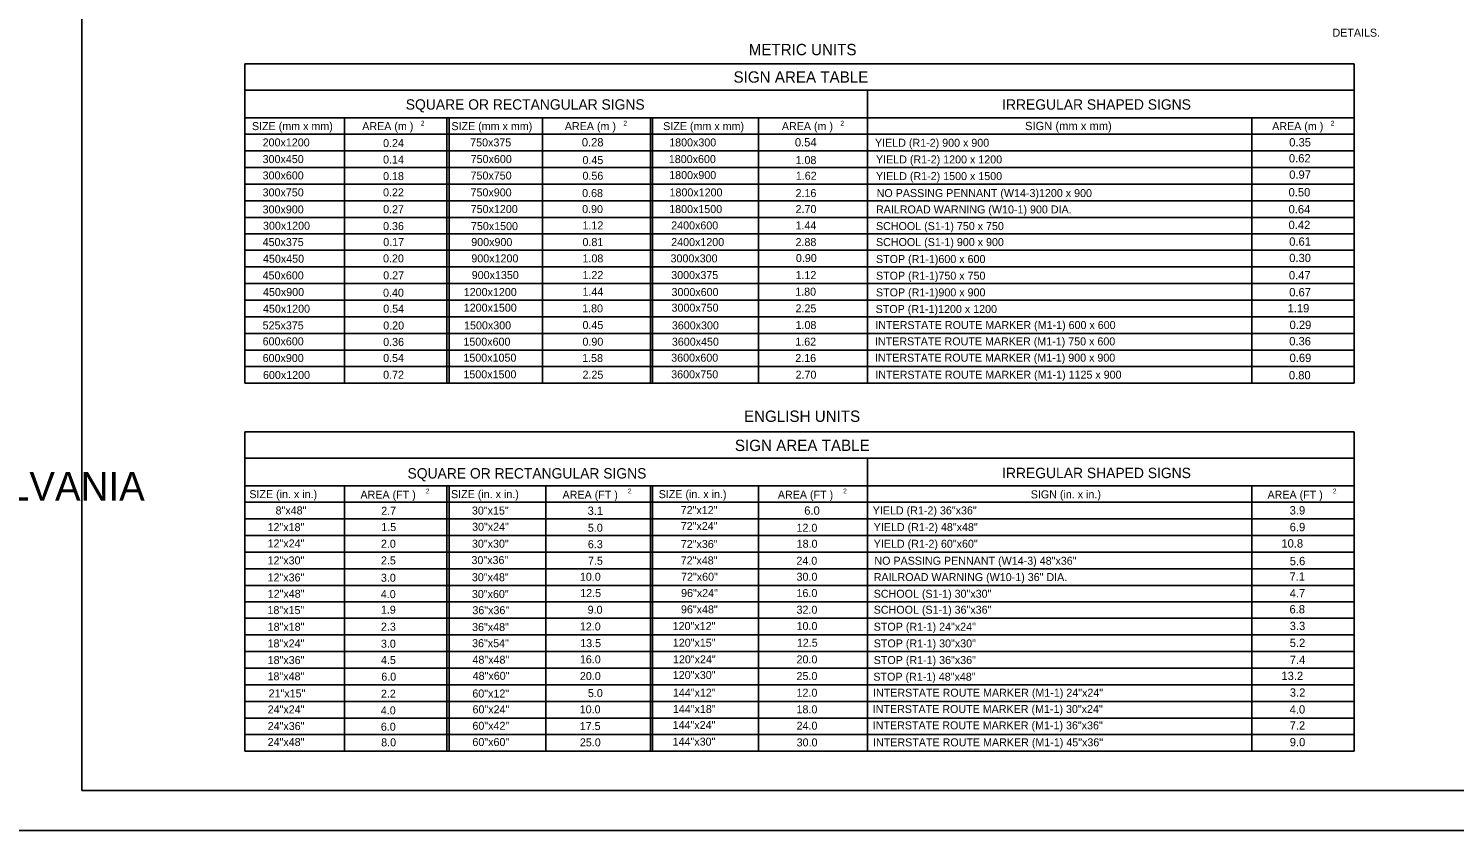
# Model space of a CAD drawing. Extents: x 644358 to 648627, y 294594 to 295782.
# Drawn here: x 645219 to 645754, y 294594 to 294894 of the extents above; entities that cross this region are included whole.
import ezdxf

# ---------------------------------------------------------------- set-up
doc = ezdxf.new("R2010")
doc.units = 0
for name, color, linetype in [('1', 7, 'Continuous'), ('2', 7, 'Continuous'), ('3', 7, 'Continuous'), ('4', 7, 'Continuous'), ('PLT-BNDY', 7, 'Continuous')]:
    doc.layers.add(name, color=color, linetype=linetype)

msp = doc.modelspace()

# ---------------------------------------------------------------- linework, layer by layer
at = {"layer": '1'}
for p, q in [((645239.31, 295172.63), (645239.31, 294608.63)), ((646025.31, 294608.63), (645239.31, 294608.63)), ((645239.31, 294608.63), (645825.31, 294608.63))]:
    msp.add_line(p, q, dxfattribs=at)
at = {"layer": '2'}
for p, q in [((645300.44, 294881.25), (645300.44, 294761.5)), ((645716.19, 294881.25), (645300.44, 294881.25)), ((645716.19, 294761.5), (645716.19, 294881.25)), ((645716.19, 294871.37), (645300.44, 294871.37)), ((645533.81, 294871.37), (645533.81, 294761.5)), ((645300.44, 294861), (645716.19, 294861)), ((645337.69, 294861), (645337.69, 294761.5)), ((645376.06, 294861), (645376.06, 294761.5)), ((645376.94, 294861), (645376.94, 294761.5)), ((645411.94, 294861), (645411.94, 294761.5)), ((645452.44, 294861), (645452.44, 294761.5)), ((645453.19, 294861), (645453.19, 294761.5)), ((645492.94, 294861), (645492.94, 294761.5)), ((645677.81, 294761.5), (645677.81, 294861)), ((645300.44, 294854.87), (645716.19, 294854.87)), ((645300.44, 294848.62), (645716.19, 294848.62)), ((645300.44, 294842.37), (645716.19, 294842.37)), ((645300.44, 294836.12), (645716.19, 294836.12)), ((645300.44, 294829.87), (645716.19, 294829.87)), ((645300.44, 294823.62), (645716.19, 294823.62)), ((645300.44, 294817.5), (645716.19, 294817.5)), ((645300.44, 294811.37), (645716.19, 294811.37)), ((645300.44, 294805.12), (645716.19, 294805.12)), ((645300.44, 294798.87), (645716.19, 294798.87)), ((645300.44, 294792.62), (645716.19, 294792.62)), ((645300.44, 294786.37), (645716.19, 294786.37)), ((645300.44, 294780.12), (645716.19, 294780.12)), ((645533.81, 294780.12), (645716.19, 294780.12)), ((645300.44, 294773.87), (645716.19, 294773.87)), ((645716.19, 294773.87), (645533.81, 294773.87)), ((645300.44, 294767.75), (645716.19, 294767.75)), ((645300.44, 294761.5), (645533.81, 294761.5)), ((645716.19, 294761.5), (645533.81, 294761.5)), ((645300.44, 294743.19), (645300.44, 294623.44)), ((645716.19, 294743.19), (645300.44, 294743.19)), ((645716.19, 294623.44), (645716.19, 294743.19)), ((645716.19, 294733.31), (645300.44, 294733.31)), ((645533.81, 294733.31), (645533.81, 294623.44)), ((645300.44, 294722.94), (645716.19, 294722.94)), ((645337.69, 294722.94), (645337.69, 294623.44)), ((645376.06, 294722.94), (645376.06, 294623.44)), ((645376.94, 294722.94), (645376.94, 294623.44)), ((645413.24, 294722.94), (645413.24, 294623.44)), ((645452.44, 294722.94), (645452.44, 294623.44)), ((645453.19, 294722.94), (645453.19, 294623.44)), ((645492.94, 294722.94), (645492.94, 294623.44)), ((645677.81, 294623.44), (645677.81, 294722.94)), ((645300.44, 294716.81), (645716.19, 294716.81)), ((645300.44, 294710.56), (645716.19, 294710.56)), ((645300.44, 294704.31), (645716.19, 294704.31)), ((645300.44, 294698.06), (645716.19, 294698.06)), ((645300.44, 294691.81), (645716.19, 294691.81)), ((645300.44, 294685.56), (645716.19, 294685.56)), ((645300.44, 294679.44), (645716.19, 294679.44)), ((645300.44, 294673.31), (645716.19, 294673.31)), ((645300.44, 294667.06), (645716.19, 294667.06)), ((645300.44, 294660.81), (645716.19, 294660.81)), ((645300.44, 294654.56), (645716.19, 294654.56)), ((645300.44, 294648.31), (645716.19, 294648.31)), ((645300.44, 294642.06), (645716.19, 294642.06)), ((645533.81, 294642.06), (645716.19, 294642.06)), ((645300.44, 294635.81), (645716.19, 294635.81)), ((645716.19, 294635.81), (645533.81, 294635.81)), ((645300.44, 294629.69), (645716.19, 294629.69)), ((645300.44, 294623.44), (645533.81, 294623.44)), ((645716.19, 294623.44), (645533.81, 294623.44))]:
    msp.add_line(p, q, dxfattribs=at)
at = {"layer": '4'}
for p, q in [((645698.96, 294800.5), (645698.96, 294800.5)), ((645698.96, 294794.25), (645698.96, 294794.25)), ((645698.96, 294788), (645698.96, 294788)), ((645698.96, 294781.75), (645698.96, 294781.75)), ((645698.96, 294775.62), (645698.96, 294775.62)), ((645698.96, 294769.37), (645698.96, 294769.37)), ((645698.96, 294763.12), (645698.96, 294763.12)), ((645354.89, 294637.31), (645354.89, 294637.31)), ((645354.89, 294631.06), (645354.89, 294631.06)), ((645354.89, 294624.81), (645354.89, 294624.81))]:
    msp.add_line(p, q, dxfattribs=at)
at = {"layer": 'PLT-BNDY'}
msp.add_lwpolyline([(645199.31, 295187.63), (646040.31, 295187.63), (646040.31, 294593.63), (645199.31, 294593.63)], close=True, dxfattribs=at)

# ---------------------------------------------------------------- texts
at = {"layer": '1'}
msp.add_text('COMMONWEALTH OF PENNSYLVANIA', height=10.7828, dxfattribs=at).set_placement((644996.9, 294717.36))
at = {"layer": '3'}
msp.add_text('DETAILS.', height=3, dxfattribs=at).set_placement((645708.03, 294891.41))
at = {"layer": '4'}
for s, height, p in [('METRIC UNITS', 4.25, (645489.24, 294884.46)), ('SIGN AREA TABLE', 4.25, (645483.55, 294874.17)), ('SQUARE OR RECTANGULAR SIGNS', 3.8872, (645360.71, 294864.05)), ('IRREGULAR SHAPED SIGNS', 3.8872, (645584.22, 294864.05)), ('SIZE (mm x mm)', 3, (645303.06, 294856.37)), ('AREA (m )', 3, (645344.39, 294856.37)), ('2', 1.8, (645366.34, 294858.06)), ('SIZE (mm x mm)', 3, (645377.81, 294856.37)), ('AREA (m )', 3, (645420.31, 294856.37)), ('2', 1.8, (645442.26, 294858.06)), ('SIZE (mm x mm)', 3, (645457.19, 294856.37)), ('AREA (m )', 3, (645501.66, 294856.37)), ('2', 1.8, (645523.61, 294858.06)), ('SIGN (mm x mm)', 3.1252, (645592.81, 294856.37)), ('AREA (m )', 3, (645685.43, 294856.37)), ('2', 1.8, (645707.38, 294858.06)), ('200x1200', 3, (645307.06, 294850.25)), ('0.24', 3, (645352.2, 294850)), ('750x375', 3, (645384.85, 294850.25)), ('0.28', 3.125, (645426.69, 294850.25)), ('1800x300', 3, (645459.44, 294850.25)), ('0.54', 3.125, (645506.54, 294850.25)), ('YIELD (R1-2) 900 x 900 ', 3, (645536.56, 294850.12)), ('0.35', 3.125, (645691.83, 294850.25)), ('300x450', 3, (645307.06, 294844)), ('0.14', 3, (645352.2, 294843.84)), ('750x600', 3, (645385.04, 294844)), ('0.45', 3, (645426.94, 294843.62)), ('1800x600', 3, (645459.31, 294844)), ('1.08', 3, (645506.79, 294843.62)), ('YIELD (R1-2) 1200 x 1200 ', 3, (645536.94, 294843.87)), ('0.62', 3.125, (645691.71, 294844.25)), ('300x600', 3, (645307.06, 294837.87)), ('0.18', 3, (645352.2, 294837.62)), ('750x750', 3, (645384.99, 294837.83)), ('0.56', 3, (645426.94, 294837.75)), ('1800x900', 3, (645459.44, 294838)), ('1.62', 3, (645506.9, 294837.75)), ('YIELD (R1-2) 1500 x 1500 ', 3, (645536.94, 294837.62)), ('0.97', 3.125, (645691.83, 294838.12)), ('300x750', 3, (645307.06, 294831.5)), ('0.22', 3, (645352.19, 294831.52)), ('750x900', 3, (645384.99, 294831.5)), ('0.68', 3, (645426.81, 294831.25)), ('1800x1200', 3, (645459.56, 294831.5)), ('2.16', 3, (645506.8, 294831.25)), ('NO PASSING PENNANT (W14-3)1200 x 900 ', 3, (645537.19, 294831.25)), ('0.50', 3.125, (645691.58, 294831.5)), ('300x900', 3, (645307.06, 294825.12)), ('0.27', 3, (645352.22, 294825.2)), ('750x1200', 3, (645385.04, 294825.25)), ('0.90', 3, (645426.81, 294825.25)), ('1800x1500', 3, (645459.44, 294825.25)), ('2.70', 3, (645506.8, 294825.25)), ('RAILROAD WARNING (W10-1) 900 DIA.', 3, (645536.94, 294825.12)), ('0.64', 3.125, (645691.58, 294825.12)), ('300x1200', 3, (645307.19, 294819)), ('0.36', 3, (645352.2, 294818.87)), ('750x1500', 3, (645385.13, 294818.86)), ('1.12', 3, (645426.94, 294819.12)), ('2400x600', 3, (645460.19, 294819.12)), ('1.44', 3, (645506.79, 294819.12)), ('SCHOOL (S1-1) 750 x 750 ', 3, (645536.94, 294818.87)), ('0.42', 3.125, (645691.58, 294819.25)), ('450x375', 3, (645307.06, 294812.87)), ('0.17', 3, (645352.26, 294812.87)), ('900x900', 3, (645385.25, 294812.87)), ('0.81', 3, (645426.94, 294812.87)), ('2400x1200', 3, (645460.19, 294812.87)), ('2.88', 3, (645506.79, 294812.87)), ('SCHOOL (S1-1) 900 x 900 ', 3, (645536.94, 294812.87)), ('0.61', 3.125, (645691.83, 294813)), ('450x450', 3, (645307.19, 294806.62)), ('0.20', 3, (645352.19, 294806.75)), ('900x1200', 3, (645385.29, 294806.75)), ('1.08', 3, (645426.94, 294806.75)), ('3000x300', 3, (645459.94, 294806.75)), ('0.90', 3, (645506.93, 294806.88)), ('STOP (R1-1)600 x 600 ', 3, (645536.94, 294806.5)), ('0.30', 3.125, (645691.83, 294806.87)), ('450x600', 3, (645307.06, 294800.37)), ('0.27', 3, (645352.26, 294800.39)), ('900x1350', 3, (645385.43, 294800.5)), ('1.22', 3, (645426.94, 294800.5)), ('3000x375', 3, (645460.19, 294800.5)), ('1.12', 3, (645506.79, 294800.5)), ('STOP (R1-1)750 x 750', 3, (645536.94, 294800.25)), ('0.47', 3.125, (645691.71, 294800.37)), ('450x900', 3, (645307.19, 294794.12)), ('0.40', 3, (645352.19, 294793.87)), ('1200x1200', 3, (645382.44, 294794.12)), ('1.44', 3, (645426.94, 294794.25)), ('3000x600', 3, (645460.31, 294794.12)), ('1.80', 3, (645506.67, 294794.25)), ('STOP (R1-1)900 x 900 ', 3, (645536.94, 294794)), ('0.67', 3.125, (645691.83, 294794)), ('1200x1500', 3, (645382.44, 294788.25)), ('3000x750', 3, (645460.31, 294788.25)), ('450x1200', 3, (645307.19, 294787.87)), ('0.54', 3, (645352.26, 294787.88)), ('1.80', 3, (645426.81, 294788)), ('2.25', 3, (645506.79, 294788)), ('STOP (R1-1)1200 x 1200', 3, (645536.81, 294787.75)), ('1.19', 3.125, (645691.21, 294788)), ('525x375', 3, (645307.06, 294781.62)), ('0.20', 3, (645352.26, 294781.57)), ('1500x300', 3, (645382.56, 294781.62)), ('0.45', 3, (645426.94, 294781.75)), ('3600x300', 3, (645460.44, 294781.62)), ('1.08', 3, (645506.79, 294781.75)), ('INTERSTATE ROUTE MARKER (M1-1) 600 x 600 ', 3, (645536.69, 294781.75)), ('0.29', 3.125, (645691.96, 294781.75)), ('600x600', 3, (645307.06, 294775.62)), ('0.36', 3, (645352.24, 294775.41)), ('1500x600', 3, (645382.31, 294775.5)), ('0.90', 3, (645426.93, 294775.5)), ('3600x450', 3, (645460.44, 294775.5)), ('1.62', 3, (645506.69, 294775.5)), ('INTERSTATE ROUTE MARKER (M1-1) 750 x 600 ', 3, (645536.56, 294775.62)), ('0.36', 3.125, (645691.83, 294775.62)), ('600x900', 3, (645307.06, 294769.37)), ('0.54', 3, (645352.22, 294769.39)), ('1500x1050', 3, (645382.31, 294769.5)), ('1.58', 3, (645426.81, 294769.37)), ('3600x600', 3, (645460.19, 294769.5)), ('2.16', 3, (645506.69, 294769.37)), ('INTERSTATE ROUTE MARKER (M1-1) 900 x 900 ', 3, (645536.56, 294769.5)), ('0.69', 3.125, (645691.96, 294769.37)), ('600x1200', 3, (645307.19, 294763)), ('0.72', 3, (645352.22, 294763.09)), ('1500x1500', 3, (645382.31, 294763.25)), ('2.25', 3, (645426.94, 294763.12)), ('3600x750', 3, (645460.19, 294763.25)), ('2.70', 3, (645506.8, 294763.12)), ('INTERSTATE ROUTE MARKER (M1-1) 1125 x 900 ', 3, (645536.69, 294763.12)), ('0.80', 3.125, (645691.71, 294762.87)), ('ENGLISH UNITS', 4.25, (645487.45, 294746.91)), ('SIGN AREA TABLE', 4.25, (645484.06, 294735.98)), ('SQUARE OR RECTANGULAR SIGNS', 3.8872, (645361.36, 294725.67)), ('IRREGULAR SHAPED SIGNS', 3.8872, (645584.22, 294725.81)), ('2', 1.8, (645368.22, 294720.08)), ('2', 1.8, (645443.95, 294720.08)), ('2', 1.8, (645524.65, 294720.08)), ('2', 1.8, (645708.17, 294720.08)), ('SIZE (in. x in.)', 3, (645302.07, 294718.31)), ('AREA (FT )', 3, (645343.73, 294718.11)), ('SIZE (in. x in.)', 3, (645377.67, 294718.31)), ('AREA (FT )', 3, (645419.46, 294718.11)), ('SIZE (in. x in.)', 3, (645455.5, 294718.31)), ('AREA (FT )', 3, (645500.16, 294718.11)), ('SIGN (in. x in.)', 3, (645594.95, 294718.24)), ('AREA (FT )', 3, (645683.68, 294718.11)), ('8"x48"', 3, (645311.91, 294712.19)), ('2.7', 3, (645351.5, 294712.07)), ('30"x15"', 3, (645385.5, 294712.15)), ('3.1', 3.125, (645428.86, 294712.02)), ('72"x12"', 3, (645463.75, 294712.32)), ('6.0', 3.125, (645510.05, 294712.08)), ('YIELD (R1-2) 36"x36" ', 3, (645535.72, 294712.2)), ('3.9', 3.125, (645691.98, 294712.18)), ('12"x18"', 3, (645308.91, 294705.94)), ('1.5', 3, (645351.53, 294705.96)), ('30"x24"', 3, (645385.56, 294706.07)), ('5.0', 3, (645428.96, 294705.7)), ('72"x24"', 3, (645463.77, 294706.36)), ('12.0', 3, (645507.16, 294705.7)), ('YIELD (R1-2) 48"x48" ', 3, (645536.09, 294705.95)), ('6.9', 3.125, (645692.01, 294705.9)), ('12"x24"', 3, (645308.91, 294699.81)), ('2.0', 3, (645351.4, 294699.7)), ('30"x30"', 3, (645385.51, 294699.72)), ('6.3', 3, (645428.96, 294699.52)), ('72"x36"', 3, (645463.79, 294699.61)), ('18.0', 3, (645507.21, 294699.7)), ('YIELD (R1-2) 60"x60" ', 3, (645536.09, 294699.7)), ('10.8', 3.125, (645688.89, 294699.77)), ('12"x30"', 3, (645308.91, 294693.44)), ('2.5', 3, (645351.4, 294693.45)), ('30"x36"', 3, (645385.33, 294693.57)), ('7.5', 3, (645429, 294693.32)), ('72"x48"', 3, (645463.76, 294693.45)), ('24.0', 3, (645507.12, 294693.32)), ('NO PASSING PENNANT (W14-3) 48"x36" ', 3, (645536.34, 294693.32)), ('5.6', 3.125, (645692.03, 294693.15)), ('12"x36"', 3, (645308.91, 294687.06)), ('3.0', 3, (645351.39, 294686.95)), ('30"x48"', 3, (645385.49, 294687.15)), ('10.0', 3, (645425.97, 294687.32)), ('72"x60"', 3, (645463.88, 294687.33)), ('30.0', 3, (645507.17, 294687.32)), ('RAILROAD WARNING (W10-1) 36" DIA.', 3, (645536.09, 294687.2)), ('7.1', 3.125, (645691.93, 294687.34)), ('12"x48"', 3, (645308.96, 294680.94)), ('4.0', 3, (645351.35, 294680.81)), ('30"x60"', 3, (645385.49, 294680.85)), ('12.5', 3, (645426.09, 294681.2)), ('96"x24"', 3, (645463.9, 294681.21)), ('16.0', 3, (645507.16, 294681.2)), ('SCHOOL (S1-1) 30"x30" ', 3, (645536.09, 294680.95)), ('4.7', 3.125, (645691.98, 294681.04)), ('18"x15"', 3, (645308.88, 294674.81)), ('1.9', 3, (645351.38, 294674.95)), ('36"x36"', 3, (645385.68, 294674.77)), ('9.0', 3, (645428.87, 294674.95)), ('96"x48"', 3, (645463.85, 294675.09)), ('32.0', 3, (645507.16, 294674.95)), ('SCHOOL (S1-1) 36"x36" ', 3, (645536.09, 294674.95)), ('6.8', 3.125, (645691.92, 294675.07)), ('18"x18"', 3, (645308.94, 294668.56)), ('2.3', 3, (645351.4, 294668.58)), ('36"x48"', 3, (645385.56, 294668.47)), ('12.0', 3, (645425.96, 294668.67)), ('120"x12"', 3, (645460.74, 294668.83)), ('10.0', 3, (645507.17, 294668.82)), ('STOP (R1-1) 24"x24" ', 3, (645536.09, 294668.57)), ('3.3', 3.125, (645692.01, 294668.81)), ('18"x24"', 3, (645308.91, 294662.31)), ('3.0', 3, (645351.4, 294662.2)), ('36"x54"', 3, (645385.56, 294662.4)), ('13.5', 3, (645426.09, 294662.42)), ('120"x15"', 3, (645460.79, 294662.58)), ('12.5', 3, (645507.29, 294662.57)), ('STOP (R1-1) 30"x30"', 3, (645536.09, 294662.32)), ('5.2', 3.125, (645692.02, 294662.45)), ('18"x36"', 3, (645308.94, 294656.06)), ('4.5', 3, (645351.4, 294656.08)), ('48"x48"', 3, (645385.71, 294656.2)), ('16.0', 3, (645425.96, 294656.32)), ('120"x24"', 3, (645460.85, 294656.34)), ('20.0', 3, (645507.17, 294656.32)), ('STOP (R1-1) 36"x36" ', 3, (645536.09, 294656.07)), ('7.4', 3.125, (645692.02, 294656.07)), ('18"x48"', 3, (645308.9, 294649.96)), ('6.0', 3, (645351.53, 294649.84)), ('48"x60"', 3, (645385.79, 294650.15)), ('20.0', 3, (645425.97, 294650.07)), ('120"x30"', 3, (645460.78, 294650.46)), ('25.0', 3, (645507.16, 294650.07)), ('STOP (R1-1) 48"x48"', 3, (645535.97, 294649.82)), ('13.2', 3.125, (645688.9, 294650.07)), ('3.2', 3.125, (645692.04, 294643.82)), ('21"x15"', 3, (645309.3, 294643.56)), ('2.2', 3, (645351.39, 294643.45)), ('60"x12"', 3, (645385.66, 294643.52)), ('5.0', 3, (645428.96, 294643.67)), ('144"x12"', 3, (645460.83, 294643.84)), ('12.0', 3, (645507.16, 294643.82)), ('INTERSTATE ROUTE MARKER (M1-1) 24"x24" ', 3, (645535.84, 294643.82)), ('24"x24"', 3, (645308.95, 294637.56)), ('4.0', 3, (645351.36, 294637.19)), ('60"x24"', 3, (645385.73, 294637.57)), ('10.0', 3, (645425.9, 294637.57)), ('144"x18"', 3, (645460.83, 294637.71)), ('18.0', 3, (645507.16, 294637.57)), ('INTERSTATE ROUTE MARKER (M1-1) 30"x24" ', 3, (645535.72, 294637.7)), ('4.0', 3.125, (645691.99, 294637.49)), ('24"x36"', 3, (645308.95, 294631.31)), ('6.0', 3, (645351.37, 294631.06)), ('60"x42"', 3, (645385.69, 294631.4)), ('17.5', 3, (645425.91, 294631.3)), ('144"x24"', 3, (645460.73, 294631.71)), ('24.0', 3, (645507.18, 294631.45)), ('INTERSTATE ROUTE MARKER (M1-1) 36"x36" ', 3, (645535.72, 294631.57)), ('7.2', 3.125, (645691.99, 294631.45)), ('24"x48"', 3, (645308.94, 294625.33)), ('8.0', 3, (645351.5, 294625.21)), ('60"x60"', 3, (645385.69, 294625.32)), ('25.0', 3, (645425.96, 294625.2)), ('144"x30"', 3, (645460.73, 294625.46)), ('30.0', 3, (645507.21, 294625.17)), ('INTERSTATE ROUTE MARKER (M1-1) 45"x36" ', 3, (645535.84, 294625.2)), ('9.0', 3.125, (645692.03, 294625.23))]:
    msp.add_text(s, height=height, dxfattribs=at).set_placement(p)

doc.saveas('drawing.dxf')
